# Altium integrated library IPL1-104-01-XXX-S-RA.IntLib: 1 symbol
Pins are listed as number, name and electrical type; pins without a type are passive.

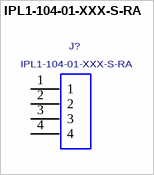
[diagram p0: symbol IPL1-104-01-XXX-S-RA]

## IPL1-104-01-XXX-S-RA
designator J?
Terminal Assembly, Single Row, Right Angle, Thru-Hole, 4 Pins.; MANUFACTURER: SAMTEC
footprint IPL1-104-01-XXX-S-RA
pins: 1, 2, 3, 4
